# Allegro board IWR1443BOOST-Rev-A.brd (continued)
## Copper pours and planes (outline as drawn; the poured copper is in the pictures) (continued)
UNNAMED_9_CAPPOLARIZED_I74_1 on TOP: 37.71,17.62 37.8,17.52 37.8,15.47 37.36,15.03 37.36,13.17 38.08,12.46 38.08,10.74 37.92,10.58 37.92,7.65 39.3,6.27 39.3,5.78 40.44,4.64 46.47,4.64 46.69,4.86 46.69,7.04 45.57,8.16 40.52,8.16 39.21,9.47 39.21,12.59 39.31,12.68 39.31,19.49 40.13,20.31 40.13,23.15 39.92,23.36 38.14,23.36 37.71,22.92
UNNAMED_9_FUSE_I161_1 on TOP: 30.19,10.85 30.19,7.01 30.37,6.83 34.49,6.83 36.53,8.88 36.53,12.7 35.45,12.7 35.38,12.62 35.38,12.24 34.33,11.2 30.55,11.2

Small or netless copper shapes (teardrops, artwork), in the pictures only: 13 on TOP

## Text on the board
Ref Des/Silkscreen Bottom: For Evaluation Only | Not FCC Approved For Resale | 3V3 | GND
User.Comments: CR_IF_2 | CR_IF-1_2 | CR_ENGINE-AREA_1 | CR_2_1 | CR_FTDI_4 | Rev-A | 1243/1443-EVM | TEXAS INSTRUMENTS | DATE: | 20/FEB/2017
Ref Des/Silkscreen Top: 1243/1443-EVM | PROC010 REV A | CAUTION HOT SURFACE | RoHS EXEMPT | GND | NERR_OUT | 5V | NRST | HD_CONN | SOP2 | CAN_H | GPIO1 | SOP1 | SOP0 | CAN_L | 5V_IN | USB
PLACE_BOUND_TOP: 4.2374 | 3.0717 | 2.6717 | 1.7076 | 4.4962 | 2.8967 | 2.4967 | 1.5620
DIMENSION: 4.0874 | 3.0554 | 2.5860 | 1.8199 | 1.4982 | 1.1548 | 0.4082 | 0.1500 | 4.3462 | 3.7554 | 2.7223 | 1.6893 | 1.5280 | 1.3526 | 1.2202 | 0.9227 | 0.2824 | 1.3199 | 2.2387 | 3.4027
User.5: 3.6374 | 2.8207 | 2.0040 | 1.0482 | 0.6524 | 3.8960 | 3.1473 | 45.0000deg | 2.2973 | 1.5486 | 0.9026 | 0.6000 | dia1.0000
User.6: 1.5026 | 1.8981 | 4.4962 | 1.6482 | 2.1199 | 4.2374
User.8: 1.0482 | 0.6524 | 315.0000deg | 3.6374 | 2.0040 | 2.8207 | R0.5625 | 0.6000 | 0.9026 | 1.5486 | 2.2973 | 3.1473 | 3.8960
User.18: J23 | J22
User.21: SHEET   1  OF  2 | OF THE BOARD. | WIDTH AND SPACING OF 4 MIL &  4 MILS. | 4.SURFACE FINISH:IMMERSION SILVER | 6.SILK SCREEN LEGEND TO BE APPLIED PER LAYER STACKUP USING WHITE | NON-CONDUCTIVE EPOXY INK. | 7.THIS PRINTED WIRING BOARD IS DESIGNED WITH A MINIMUM CONDUCTOR | 13. TRACE WIDTH SHOULD BE ACCURATELY ETCHED. MAX TOLERANCE +/- 1 MIL | 12.MANUFACTURER'S IDENTIFICATION,DATECODE LETTER SHALL BE SILKSCREENED ON SOLDER SIDE | 14.BOARD DIMENSIONS ARE IN (INCHES). | 16.PCB Material must meet or exceed UL94V-0 requirements. | 15.BOW AND TWIST SHALL NOT EXCEED 0.7% OF LONGEST SIDE | 11.VENDOR SHOULD FOLLOW ROHS COMPLIANT PROCESS AND Pb FREE FOR MANUFACTURING | 17.LAYER TO LAYER REGISTRATION SHALL BE WITHIN +/-2 MIL | 18.REFER STACKUP DOCUMEMENT FOR IMPEDENCE CONTROL TRACES ON LAYER 1. | NOTES: UNLESS OTHERWISE SPECIFIED. | 10. SOLDER MASK OPENING IS KEPT SAME SIZE AS PAD (1:1) FOR ALL COMPONENTS EXCEPT U2 | 19.FOR ANTENNA ETCHING TOLERANCE REFER "ANTENNA ETCHING REQUIREMETS"DOCUMENT. | 5.SOLDERMASK ON BOTH SIDES OF THE BOARD SHALL BE LPI, COLOR RED. | 3.PRINTED WIRING BOARD SHALL COMPLY WITH REQUIREMENTS OF ANSI/J-STD-003. | 1.FABRICATE PER IPC-6012A CLASS 2. | 2. FOR BOARD THICKNESS AND IMPEDANCE DETAILS REFER STACKUP DOCUMENT. | 8.ALL VIAS ARE TENTED ON BOTH SIDES UNLESS SOLDERMASK OPENED IN GERBER. | 9.ALL VIAS ON PAD SHOULD BE FILLED WITH NON CONDUCTIVE EPOXY AND SURFACE SHOULD BE FLAT | 50 OHM SINGLE ENDED AND 10OHM DIFFERENTIAL IMPEDENCE CONTROL TRACES. | PCB must bear the UL94V-0 registered material ID number. | REFER VIA FILL DOCUMENT TO IDENTIFY THE VIAS TO BE FILLED | FLATNESS TOLERANCE FOR VIA ON PADS: +0.000 /- 0.001 INCHES ON BOTH SIDES. | THE MANUFACTURER IS REQUESTED TO SIZE IT AS PER THEIR SOLDERMASK TOLERANCE. | FOR U2 (BGA) PLEASE FOLLOW SAME SOLDERMASK SIZE AS GERBER | FABRICATION DRAWING-1
User.22: SHEET   2  OF  2 | FABRICATION DRAWING-2
User.23: ASSEMBLY | BOTTOM
User.24: ASSEMBLY | TOP
User.25: LAYER-1 | TOP
User.26: LAYER-2 | GROUND
User.27: GND/SIGNAL | LAYER-3
User.28: GND/SIGNAL | LAYER-4
User.29: LAYER-5 | GROUND
User.30: LAYER-6 | BOTTOM
User.31: SOLDERMASK | BOTTOM
User.32: SOLDERMASK | TOP
User.33: SOLDERPASTE | BOTTOM
User.34: SOLDERPASTE | TOP
User.35: SILKSCREEN | BOTTOM
User.36: SILKSCREEN | TOP
User.38: OUTLINE | BOARD
User.40: UNLESS OTHERWISE SPECIFIED | INCHES | ALL DIMENSIONS ARE IN | X | MILLIMETERS | SIZE | SCALE | DRAWING TITLE | PART NUMBER | 1/1 | REV | A | D | 20/02/2017 | DATE | TEXAS INSTRUMENTS | 1243/1443-EVM | CAD | DATA | DO NOT MANUALLY | UPDATE | C | B | 8 | 7 | 6 | 5 | 4 | 3 | 2 | 1
User.43: FIGURE | SIZE | 5.9 | DRILL CHART: TOP to L2 | ALL UNITS ARE IN MILS | TOLERANCE | +0.0/-5.9 | PLATED | QTY | 510
User.44: FIGURE | SIZE | 12.2 | 33.46 | 40.16 | 40.2 | 43.31 | 47.33 | 157.48 | 160.0 | 51.18x23.62 | 118.11x39.37 | 137.8x39.37 | DRILL CHART: TOP to BOTTOM | ALL UNITS ARE IN MILS | TOLERANCE | +0.0/-12.2 | +2.0/-2.0 | +2.99/-2.99 | PLATED | NON-PLATED | QTY | 635 | 2 | 3 | 8 | 4 | 1
